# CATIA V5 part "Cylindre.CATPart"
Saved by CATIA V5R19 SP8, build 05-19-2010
Part number: Cylindre
Bounding box of the stored display mesh (mm): x -105 to 105, y -110.99 to 119.01, z -1400.007 to -830.007
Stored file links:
  G:\EU_thinkMotion\CFAO_2010\MMS_groupe3\MMS_groupe3\rdalborgo\rdalborgo\Cylindre.CATPart
  G:\EU_thinkMotion\CFAO_2010\MMS_groupe3\MMS_groupe3\rdalborgo\rdalborgo\rdalborgo.CATProduct
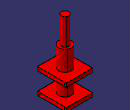
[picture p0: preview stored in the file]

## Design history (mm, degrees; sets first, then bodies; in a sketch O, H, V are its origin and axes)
External parameters (linked from other documents)
  `External.Largeur bielle` = 210 mm
Set1
  Plane1: stored without definition
Set2
  Plane2 to Plane4: linked copy from another document
  Line1: linked copy from another document
  Point1: linked copy from another document
Body1 (main body)
  Sketch1 on Plane2, origin (0, 0, 0), H (0, 1, 0), V (0, 0, 1)
    line L1 (-110.9904, -1200.0067) -> (119.0096, -1200.0067)
    line L2 (119.0096, -1200.0067) -> (119.0096, -1230.0067)
    line L3 (119.0096, -1230.0067) -> (-110.9904, -1230.0067)
    line L4 (-110.9904, -1230.0067) -> (-110.9904, -1200.0067)
    line L5 (-110.9904, -1370.0067) -> (119.0096, -1370.0067)
    line L6 (119.0096, -1400.0067) -> (-110.9904, -1400.0067)
    line L7 (119.0096, -1370.0067) -> (119.0096, -1400.0067)
    line L8 (-110.9904, -1400.0067) -> (-110.9904, -1370.0067)
    reference intersected line E1 through (0, -1300.0067) direction (-1, 0) from Plane3
    reference intersected line E2 through (0, -1300.0067) direction (-1, 0) from Plane3
    reference intersected line E3 through (4.0096, 0) direction (0, 1) from Plane4
    reference intersected line E4 through (4.0096, 0) direction (0, 1) from Plane4
    distance L3 L1 = 30
    distance L4 L2 = 230
    distance L6 L5 = 30
    distance L8 L7 = 230
    distance L6 E1 = 100
    distance L1 E2 = 100
    distance L2 E3 = 115
    distance L7 E4 = 115
    horizontal: L1 H, L3 H, L5 H, L6 H
    vertical: L2 V, L4 V, L7 V, L8 V
  Pad1: profile Sketch1, direction (1, 0, 0), length 105 {= `External.Largeur bielle` /2}, mirrored extent
  Sketch2 on start face of Pad1, origin (-105, 95.1207, -1202.593), H (0, 1, 0), V (0, 0, -1)
    point P1 (8.8888, 12.4137)
    reference projected line E1 (-91.1112, -372.593) -> (-91.1112, 297.407) from Line1
    reference intersected line E2 through (0, 97.4137) direction (1, 0) from Plane3
    distance P1 E1 = 100
    distance P1 E2 = 85
  Hole1: placed by Sketch2, at (-105, 104.0096, -1215.0067) direction (1, 0, 0), diameter 10, through (limit type 3)
  RectPattern1: of Hole1, direction 1 instances 2, spacing 200, along Plane2 reversed, direction 2 instances 2, spacing 170, along Plane2 reversed
  Sketch3 on face of Pad1 from Sketch1.L1, origin (0, 0, -1200.0067), H (1, 0, 0), V (0, 1, 0)
    circle A1 centre (0, 4.0096) radius 50
    point P1 (0, 4.0096)
    point P2 (49.839, 0)
    reference projected point E1 (0, 4.0096) from Line1
    radius A1 = 50
    coincidence: A1 P2, P2 H, P1 E1
  Pocket1: profile Sketch3, direction (0, 0, -1), through (limit type 3)
  Sketch4 on Plane2, origin (0, 0, 0), H (0, 1, 0), V (0, 0, 1)
    line L1 (9.0096, -1040.0067) -> (9.0096, -1050.0067)
    line L2 (9.0096, -1050.0067) -> (34.0096, -1050.0067)
    line L3 (34.0096, -1050.0067) -> (34.0096, -1400.0067)
    line L4 (34.0096, -1400.0067) -> (54.0096, -1400.0067)
    line L5 (34.0096, -830.0067) -> (4.0096, -830.0067)
    point P7 (4.0096, -830.0067)
    line L6 (4.0096, -830.0067) -> (4.0096, -840.0067)
    line L7 (4.0096, -840.0067) -> (24.0096, -840.0067)
    line L8 (24.0096, -840.0067) -> (24.0096, -1040.0067)
    line L9 (24.0096, -1040.0067) -> (9.0096, -1040.0067)
    reference projected line E1 (4.0096, -830) -> (4.0096, -1500) from Line1
    reference projected point E2 (4.0096, -830.0067) from Point1
    reference projected line E3 (4.0096, -830) -> (4.0096, -1500) from Line1
    reference projected line E4 (4.0096, -830) -> (4.0096, -1500) from Line1
    reference intersected line E5 through (0, -1300.0067) direction (-1, 0) from Plane3
    reference projected line E6 (4.0096, -830) -> (4.0096, -1500) from Line1
    line L10 (34.0096, -830.0067) -> (34.0096, -1040.0067)
    line L11 (34.0096, -1040.0067) -> (54.0096, -1040.0067)
    line L12 (54.0096, -1040.0067) -> (54.0096, -1400.0067)
    distance L7 L5 = 10
    distance L9 L2 = 10
    distance L1 E3 = 5
    distance L9 L7 = 200
    distance L8 E4 = 20
    distance L4 E5 = 100
    distance L3 E6 = 30
    distance L3 L12 = 20
    distance L10 L8 = 10
    vertical: L1 V, L3 V, L6 V, L8 V, L10 V, L12 V
    horizontal: L2 H, L4 H, L5 H, L7 H, L9 H, L11 H
    coincidence: L6 E1, P7 E2, L11 L9
  Shaft1: profile Sketch4, axis Line1, angle 360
